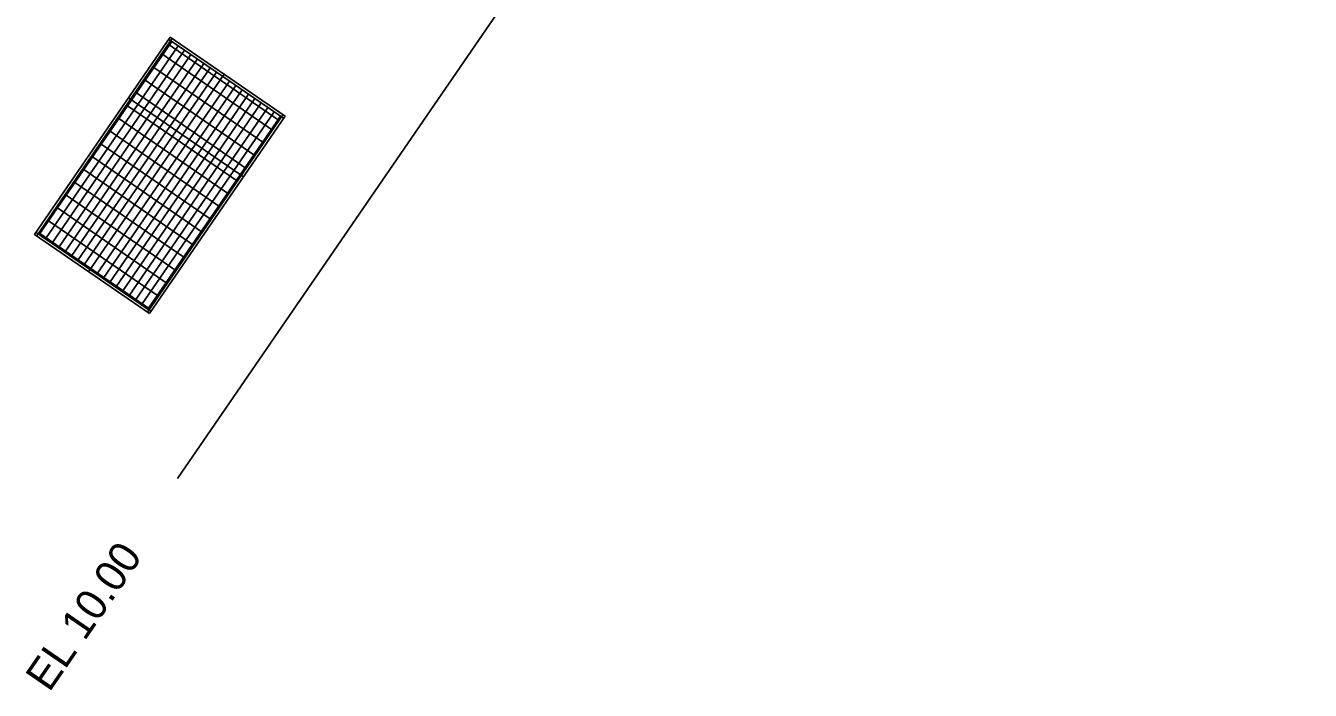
# Model space of a CAD drawing. Extents: x 2378999 to 2381348, y 331302 to 333122.
# Drawn here: x 2379517 to 2379599.9, y 331805.4 to 331848.3 of the extents above; entities that cross this region are included whole.
import ezdxf

# ---------------------------------------------------------------- set-up
doc = ezdxf.new("R2010")
doc.units = 0
for name, color, linetype in [('Mis Work Point CELL', 7, 'Continuous'), ('P_SMU_Rebar_B_Bar', 7, 'Continuous'), ('P_SMU_Rebar_H_Bar', 7, 'Continuous'), ('P_SMU_Rebar_V_Bar', 7, 'Continuous'), ('Scratch_Level_0', 7, 'Continuous'), ('Sup Concrete Slab Lines', 7, 'Continuous')]:
    doc.layers.add(name, color=color, linetype=linetype)

msp = doc.modelspace()

# ---------------------------------------------------------------- linework, layer by layer
at = {"layer": 'Mis Work Point CELL'}
msp.add_line((2379526.805, 331819.101), (2379599.933, 331925.541), dxfattribs=at)
at = {"layer": 'P_SMU_Rebar_B_Bar'}
for p, q in [((2379517.579, 331834.849), (2379526.329, 331847.584)), ((2379526.329, 331847.584), (2379533.754, 331842.482)), ((2379529.823, 331845.183), (2379521.073, 331832.448)), ((2379523.637, 331843.665), (2379531.062, 331838.564)), ((2379533.754, 331842.482), (2379525.005, 331829.747)), ((2379517.579, 331834.849), (2379525.005, 331829.747))]:
    msp.add_line(p, q, dxfattribs=at)
at = {"layer": 'P_SMU_Rebar_H_Bar'}
for p, q in [((2379517.88, 331834.845), (2379526.44, 331847.305)), ((2379518.292, 331834.561), (2379526.852, 331847.022)), ((2379518.704, 331834.278), (2379527.265, 331846.738)), ((2379519.116, 331833.995), (2379527.677, 331846.455)), ((2379519.528, 331833.712), (2379528.089, 331846.172)), ((2379519.94, 331833.429), (2379528.501, 331845.889)), ((2379520.352, 331833.146), (2379528.913, 331845.606)), ((2379520.764, 331832.863), (2379529.325, 331845.323)), ((2379530.157, 331844.751), (2379521.596, 331832.291)), ((2379530.569, 331844.468), (2379522.008, 331832.008)), ((2379530.981, 331844.185), (2379522.42, 331831.725)), ((2379531.393, 331843.902), (2379522.832, 331831.442)), ((2379531.805, 331843.619), (2379523.245, 331831.159)), ((2379532.217, 331843.336), (2379523.657, 331830.876)), ((2379532.629, 331843.053), (2379524.069, 331830.592)), ((2379533.042, 331842.769), (2379524.481, 331830.309)), ((2379533.454, 331842.486), (2379524.893, 331830.026))]:
    msp.add_line(p, q, dxfattribs=at)
at = {"layer": 'P_SMU_Rebar_V_Bar'}
for p, q in [((2379526.211, 331847.118), (2379533.361, 331842.205)), ((2379525.786, 331846.499), (2379532.937, 331841.587)), ((2379525.22, 331845.675), (2379532.37, 331840.762)), ((2379524.653, 331844.851), (2379531.804, 331839.938)), ((2379524.087, 331844.027), (2379531.238, 331839.114)), ((2379523.521, 331843.203), (2379530.672, 331838.29)), ((2379522.955, 331842.378), (2379530.105, 331837.466)), ((2379522.388, 331841.554), (2379529.539, 331836.641)), ((2379521.822, 331840.73), (2379528.973, 331835.817)), ((2379521.256, 331839.906), (2379528.406, 331834.993)), ((2379520.69, 331839.081), (2379527.84, 331834.169)), ((2379520.123, 331838.257), (2379527.274, 331833.344)), ((2379519.557, 331837.433), (2379526.708, 331832.52)), ((2379518.991, 331836.609), (2379526.141, 331831.696)), ((2379518.424, 331835.785), (2379525.575, 331830.872)), ((2379517.858, 331834.96), (2379525.009, 331830.048))]:
    msp.add_line(p, q, dxfattribs=at)
at = {"layer": 'Scratch_Level_0'}
for p, q in [((2379517.717, 331834.754), (2379526.466, 331847.489)), ((2379526.234, 331847.446), (2379533.66, 331842.345)), ((2379533.617, 331842.576), (2379524.867, 331829.842)), ((2379517.674, 331834.986), (2379525.099, 331829.885))]:
    msp.add_line(p, q, dxfattribs=at)

# ---------------------------------------------------------------- texts
at = {"layer": 'Sup Concrete Slab Lines'}
msp.add_text('EL 10.00', height=2, rotation=55.50932, dxfattribs=at).set_placement((2379518.532, 331805.267))

doc.saveas('drawing.dxf')
